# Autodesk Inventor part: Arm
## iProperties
Created: 2002-01
Part Number: Arm
Document SubType Name: Modeling
Designer: ***
Control State: 0
Master: False
Checked Out: False
Shininess: 20.0
Length Units: 11269
Angle Units: 11279
Time Units: 11290
Mass Units: 11283
Length Display Precision: 3
Angle Display Precision: 2
Density: 0.0
Volumn: 0.0
Area: 0.0
PropertySet Name: Model Information
Author: ***
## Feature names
1. Extrusion1
2. Extrusion2
